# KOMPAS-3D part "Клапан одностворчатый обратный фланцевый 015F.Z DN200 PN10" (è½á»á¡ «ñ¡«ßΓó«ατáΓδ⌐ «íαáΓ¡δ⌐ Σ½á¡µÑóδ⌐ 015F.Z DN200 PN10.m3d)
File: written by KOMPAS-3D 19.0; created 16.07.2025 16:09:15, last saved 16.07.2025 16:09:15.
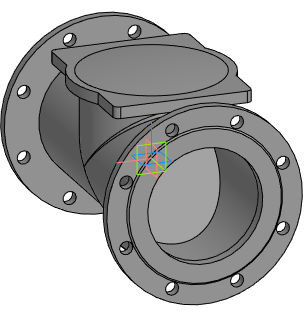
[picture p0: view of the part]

Document properties: Полное имя файла: E:\Dendor Работа Сачек\3D для проектировщиков\5.4 Тип 015F.Z. Клапан одностворчатый обратный фланцевый\stp_Клапан одностворчатый обратный фланцевый 015F.Z PN10_16\Клапан одностворчатый обратный фланцевый 015F.Z DN200 PN10.m3d

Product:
- Part/product: Клапан одностворчатый обратный фланцевый 015F.Z DN200 PN10

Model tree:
1. Операция без истории:1  (labels: Клапан одностворчатый обратный фланцевый 015F.Z DN200 PN10)
2. Операция без истории:2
